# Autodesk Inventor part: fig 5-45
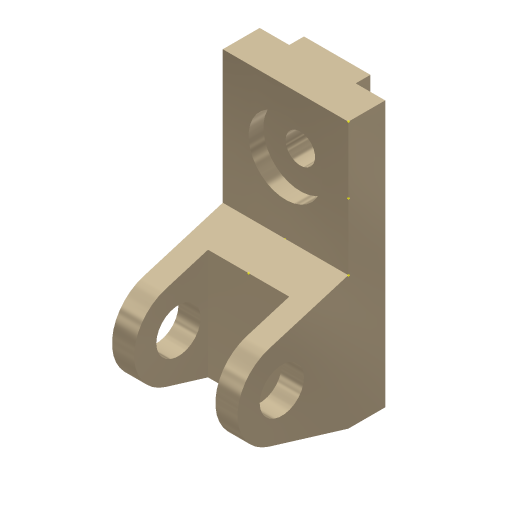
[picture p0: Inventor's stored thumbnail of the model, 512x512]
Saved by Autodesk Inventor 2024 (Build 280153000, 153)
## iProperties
Shininess: 65.0
Angle Display Precision: 2
Document Length Units: 11269
Document Angle Units: 11279
Document Time Units: 11290
Document Mass Units: 11283
Document Length Units Precision: 3
Document Angle Units Precision: 2
Created: 2001-11
Part Number: fig 5-45
Document SubType Name: Modeling
Designer: Renu Muthoo
Density: 1 g/cm^3
Material: Generic
Appearance: Metal-Titanium (Polished)
Density: 0.0
Volumn: 0.0
Area: 0.0
PropertySet Name: Model Information
Control State: 0
Master: False
Checked Out: False
Author: Renu Muthoo
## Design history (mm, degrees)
sketch "Sketch2"
  geometry: L1 (33.257, 104.664)-(33.257, -75.336); L2 (33.257, -75.336)-(8.257, -75.336); L3 (8.257, -75.336)-(-45.451, -59.045); L4 (-45.451, -1.628)-(8.257, 14.664); L5 (8.257, 14.664)-(8.257, 104.664); L6 (8.257, 104.664)-(33.257, 104.664); C1 r 15 at (-36.743, -30.336); A1 r 30 centre (-36.743, -30.336) between (-45.451, -1.628) and (-45.451, -59.045)
  constraints: 12 end point, 2 centre point, 2 equal length, 2 parallel, 2 point on circle, 2 tangent, 1 coincident, 1 perpendicular, 1 vertical
  dimensions: "d0" = 180 distance of L1.start L1.end; "d1" = 30 radius of A1; "d2" = 25 distance of L5.end L1.start; "d3" = 45 distance from line of L2 A1.centre; "d4" = 70 distance from line of L1 A1.centre; "d5" = 30 diameter of C1
extrude "Extrusion1" new body sketch "Sketch2" distance "d6" = 85; taper "d7" = 0 deg
workplane "Work Plane1"
sketch "Sketch3"
  geometry: L1 (15, 62.364)-(70, 62.364); L2 (70, 62.364)-(70, -52.386); L3 (70, -52.386)-(15, -52.386); L4 (15, -52.386)-(15, 62.364); L5 (0, -45)-(0, -28.708) reference
  constraints: 8 end point, 2 parallel, 1 horizontal, 1 perpendicular
  dimensions: "d8" = 55 distance of L1.start L1.end; "d9" = 15 distance between parallel lines of L5 L4
extrude "Extrusion2" cut sketch "Sketch3" distance "d10" = 50; taper "d11" = 0 deg
sketch "Sketch4"
  geometry: L1 (0, 25)-(85, 25) reference; L2 (0, 0)-(0, 25) reference; L3 (20, 25)-(65, 25); L4 (65, 25)-(65, 35); L5 (65, 35)-(20, 35); L6 (20, 35)-(20, 25)
  constraints: 8 end point, 2 parallel, 1 horizontal, 1 perpendicular, 1 point on line
  dimensions: "d12" = 45 distance of L4.end L5.end; "d13" = 10 distance of L3.end L4.end; "d14" = 20 distance between parallel lines of L2 L6
extrude "Extrusion3" join sketch "Sketch4" stored distance "d15" = 50; taper "d16" = 0 deg
sketch "Sketch5"
  geometry: L1 (85, 0)-(85, 90) reference; L2 (0, 90)-(85, 90) reference; 1 further point
  dimensions: "d17" = 42 distance from line of L2 point (42.5, 48); "d18" = 42.5 distance from line of L1 point (42.5, 48)
hole "Hole1" sketch "Sketch5" diameter "d19" = 20; stored, may be unused: countersink angle "d23" = 82 deg, drill point angle "d25" = 118 deg; dims "d20" = 6, "d21" = 50, "d22" = 10, "d24" = 8
workpoint "Work Point1"
workpoint "Work Point2"
workpoint "Work Point3"
workpoint "Work Point4"
workpoint "Work Point5"
body "Solid1"
node "Sketch1"
